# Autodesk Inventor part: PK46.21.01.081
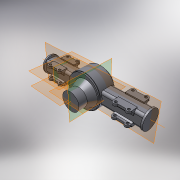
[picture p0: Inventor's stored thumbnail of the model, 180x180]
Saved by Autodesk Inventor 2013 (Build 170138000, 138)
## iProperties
Created: 2005-03
Part Number: PK46.21.01.081
Material: Steel, Mild
Document SubType Name: Modeling
Designer: salex
Manufacturer: Standard
Standards Organization: Custom
Density: 7.86 g/cm^3
Author: salex
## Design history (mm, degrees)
sketch "Эскиз1"
  geometry: L1 (0, 0)-(0, 183); L2 (0, 0)-(107.5, 0); L3 (107.5, 0)-(107.5, 100); L4 (107.5, 100)-(152.5, 183); L5 (152.5, 183)-(0, 183); L6 (295.69, 299)-(-200.814, 299); L7 (247.792, -104)-(-137.729, -104)
  constraints: 14 end point, 3 perpendicular, 2 parallel, 1 vertical, 1 other
  dimensions: "d1" = 215 diameter of L3 L1; "d3" = 305 diameter of L4.end L1; "d4" = 100 distance of L2.end L3.end; "d25" = 403 distance between parallel lines of L6 L7 (= d8); "d26" = 116 distance between parallel lines of L5 L6; "d27" = 104 distance between parallel lines of L7 L2 (= d9)
revolve "Вращение1" sketch "Эскиз1" stored, may be unused: angle "d6" = 90 deg
node "РабОсь1"
sketch "Эскиз2"
  geometry: L1 (0, 514.15)-(0, -151.55) reference; L2 (-152.5, 183)-(152.5, 183) reference; L3 (-30, 183)-(-30, 512.027); L4 (-30, 183)-(167.5, 183); L5 (167.5, 183)-(167.5, 199); L6 (167.5, 199)-(175, 199); L7 (175, 199)-(175, 389); L8 (-30, 509)-(99.414, 509); L9 (-240.7, 299)-(256.023, 299); L10 (-157.419, -104)-(169.635, -104); L11 (-107.5, 0)-(107.5, 0) reference; L12 (155, 389)-(175, 389); L13 (-30, 183)-(-30, 169.877); A1 r 202.604 centre (-30, 306.396) between (155, 389) and (-30, 509)
  constraints: 20 end point, 6 parallel, 3 perpendicular, 2 point on circle, 2 point on line, 1 centre point, 1 tangent
  dimensions: "d7" = 210 distance between parallel lines of L8 L9; "d8" = 403 distance between parallel lines of L9 L10; "d9" = 104 distance between parallel lines of L11 L10; "d12" = 395 diameter of L5 L3; "d13" = 30 distance between parallel lines of L1 L13; "d15" = 370 diameter of L12.start L3; "d24" = 410 diameter of L7 L3; "d28" = 100 distance between parallel lines of L6 L9; "d29" = 90 distance between parallel lines of L9 L12
revolve "Вращение2" sketch "Эскиз2" stored, may be unused: angle "d18" = 90 deg
node "РабОсь2"
node "РабПлоскость1"
sketch "Эскиз3"
  geometry: L1 (-85, -612.5)-(75, -612.5); L2 (75, -612.5)-(75, 672.5); L3 (75, 672.5)-(-85, 672.5); L4 (-85, 672.5)-(-85, -612.5); L5 (-367.7, 30)-(344.9, 30) reference; L6 (398, 362.151)-(398, -222.344); L7 (-5, 672.5)-(-5, -612.5); L8 (294, -77.5)-(294, 137.5) reference
  constraints: 12 end point, 2 midpoint, 2 parallel, 2 perpendicular, 1 horizontal
  dimensions: "d19" = 642.5 distance between parallel lines of L1 L5; "d20" = 642.5 distance between parallel lines of L3 L5 (= d19); "d21" = 160 distance of L2.end L3.end; "d22" = 403 distance between parallel lines of L7 L6 (= d8); "d23" = 104 distance between parallel lines of L6 L8 (= d9)
extrude "Выдавливание1" join sketch "Эскиз3" stored distance "d30" = 160 (= d21); taper "d31" = 0 deg
node "РабПлоскость3"
node "РабПлоскость4"
sketch "Эскиз5"
  geometry: L1 (-5, -622.453)-(-5, 638.532); L2 (294, -77.5)-(294, 137.5) reference
  constraints: 2 end point, 1 vertical
  dimensions: "d37" = 299 distance between parallel lines of L1 L2 (= d8 - d9)
  node "Спроецированная петля1"
node "РабОсь4"
sketch "Эскиз6"
  geometry: L1 (-130, -441.716)-(-130, -358.284); L2 (-120, -500)-(-50, -500); L3 (-50, -500)-(-50, -300); L4 (-50, -300)-(-120, -300); L5 (-5, -751.948)-(-5, 1060.986) reference; L6 (344.9, 30)-(-367.7, 30) reference; A1 r 30 centre (-120, -470) between (-130, -441.716) and (-120, -500); A2 r 30 centre (-120, -330) between (-120, -300) and (-130, -358.284)
  constraints: 8 end point, 4 point on circle, 3 perpendicular, 2 centre point, 2 tangent, 1 equal radius, 1 vertical
  dimensions: "d38" = 140 distance of A2.centre A1.centre; "d39" = 30 radius of A1; "d40" = 115 distance from line of A1.centre L5; "d41" = 70 distance from line of A1.centre L3; "d42" = 0 horizontal distance of A2.centre A1.centre; "d44" = 10 distance from line of A2.centre L1; "d45" = 500 distance from line of A1.centre L6
extrude "Выдавливание2" join sketch "Эскиз6" distance "d46" = 25; taper "d47" = 0 deg
node "РабПлоскость5"
sketch "Эскиз7"
  geometry: L1 (-85, -500)-(-85, -300) reference; L2 (-120, -500)-(-85, -500) reference; L3 (-130, -358.284)-(-130, -441.716) reference; L4 (-85, -300)-(-120, -300) reference; A1 r 30 centre (-120, -470) between (-130, -441.716) and (-120, -500) reference; A2 r 30 centre (-120, -330) between (-120, -300) and (-130, -358.284) reference
extrude "Выдавливание3" join sketch "Эскиз7" distance "d49" = 25; taper "d50" = 0 deg
node "РабПлоскость6"
mirror "ЗеркОтобр1"
sketch "Эскиз8"
  geometry: L1 (300, -110)-(300, -75) reference; L2 (500, -75)-(500, -110) reference; L3 (612.5, -75)-(500, -75) reference; L4 (500, 85)-(612.5, 85) reference; L5 (500, 85)-(500, 120) reference; L6 (300, 120)-(300, 85) reference; L7 (500, 97)-(300, 97); L8 (500, -87)-(300, -87); L9 (500, 97)-(500, -87); L10 (300, 91.158)-(300, -87)
  constraints: 8 end point, 5 point on line, 3 perpendicular, 1 parallel
  dimensions: "d52" = 12 distance between parallel lines of L4 L7; "d53" = 12 distance between parallel lines of L3 L8 (= d52)
extrude "Выдавливание4" join sketch "Эскиз8" distance "d54" = 14; taper "d55" = 0 deg
sketch "Эскиз9"
  geometry: L1 (-441.716, -120)-(-358.284, -120) reference; L2 (-300, -110)-(-300, -40) reference; L3 (-300, -40)-(-500, -40) reference; L4 (-500, -40)-(-500, -110) reference; C1 r 15 at (-470, 120); C2 r 15 at (-330, 120); C3 r 15 at (-470, -110); C4 r 15 at (-330, -110); A1 r 30 centre (-470, 120) between (-441.716, 130) and (-500, 120) reference; A2 r 30 centre (-330, 120) between (-300, 120) and (-358.284, 130) reference; A3 r 30 centre (-330, -110) between (-358.284, -120) and (-300, -110) reference; A4 r 30 centre (-470, -110) between (-500, -110) and (-441.716, -120) reference
  constraints: 4 centre point, 4 coincident, 3 equal radius
  dimensions: "d56" = 30 diameter of C1
extrude "Выдавливание5" cut sketch "Эскиз9" stored distance "d57" = 14; taper "d58" = 0 deg
mirror "ЗеркОтобр2"
node "РабПлоскость7"
mirror "ЗеркОтобр3"
sketch "Эскиз12"
  geometry: L1 (-5, 25)-(25, 25) reference; L2 (45, 15)-(45, 25) reference; L3 (45, 25)-(45, 15) reference; L4 (45, 175)-(45, 15) reference; L5 (45, 175)-(45, 150) reference; L6 (45, 150)-(45, 175) reference; L7 (45, 15)-(45, 175) reference; L8 (-5, 25)-(25, 25) reference; L9 (-5, 25)-(25, 25) reference; L10 (45, 25)-(10, 25) reference; L11 (10, 25)-(0, 25) reference; L12 (0, 25)-(10, 25) reference; L13 (10, 25)-(45, 25) reference; L14 (25, 150)-(-5, 150) reference; L15 (25, 150)-(-5, 150) reference; L16 (25, 150)-(-5, 150) reference; L17 (45, 150)-(10, 150) reference; L18 (10, 150)-(0, 150) reference; L19 (0, 150)-(10, 150) reference; L20 (10, 150)-(45, 150) reference; L21 (27.5, 150)-(45, 140); L22 (45, 140)-(45, 150); L23 (27.5, 150)-(45, 150); L24 (27.5, 25)-(35, 65); L25 (35, 65)-(45, 65); L26 (45, 65)-(45, 25); L27 (27.5, 25)-(45, 25)
  constraints: 14 end point, 4 collinear, 2 midpoint, 2 point on line, 1 perpendicular
  dimensions: "d70" = 40 distance between parallel lines of L13 L25; "d71" = 10 distance of L24.end L25.end; "d72" = 10 distance from line of L20 L21.end
extrude "Выдавливание8" join sketch "Эскиз12" stored distance "d73" = 200; taper "d74" = 0 deg
mirror "ЗеркОтобр4"
mirror "ЗеркОтобр5"
fillet "Сопряжение4" dims "d75" = 30
sketch "Эскиз13"
  geometry: C1 r 110 at (-80, 50); 1 further point
  constraints: 1 centre point, 1 coincident
  dimensions: "d76" = 220 diameter of C1
extrude "Выдавливание9" join sketch "Эскиз13" distance "d77" = 20; taper "d78" = 0 deg
mirror "ЗеркОтобр6"
body "Solid1"
node "Спроецированная петля2"
node "Спроецированная петля3"
node "Спроецированная петля8"
node "Спроецированная петля9"
node "Спроецированная петля10"
other parameters: "d32" = 95, "d33" = 90 deg, "d48" = -175, "d51" = 90 deg
